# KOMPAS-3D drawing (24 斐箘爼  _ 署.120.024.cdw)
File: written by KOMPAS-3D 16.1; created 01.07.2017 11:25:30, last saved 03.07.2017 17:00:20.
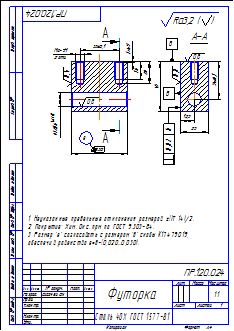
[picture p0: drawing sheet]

Sheet 1: A4, portrait

Title block, sheet 1: name: Футорка; designation: ПР.120.024; material: Сталь 40Х ГОСТ 1577-81; scale: 1:1; sheets: 1; sheet format: A4; stored path: D:\VSE\Эрга\Оснастка\Гибка лепестков\Прохвост\Скоба _ К17.479.019.cdw; drawn by: Сигачев СИ

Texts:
  Sergey
  Неуказанные предельные отклонения размеров  (IT 14)/2.
  Покрытие: Хим. Окс. прм по ГОСТ 9.303-84.
  Размер "е" согласовать с размером "д" скобы К17.479.019,
  обеспечив равенство е=д-(0,020...0,030).
  Ra3,2
  Ra3,2 ( )
Dimensions and other numbers on the sheet: 34±0,1; 45; 12,5; 25; 0,8; 0,02; 1; -7Н; 8; 2 отв.; 35±0,1; 16; 20; 12; 0,4; 50; 1:1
